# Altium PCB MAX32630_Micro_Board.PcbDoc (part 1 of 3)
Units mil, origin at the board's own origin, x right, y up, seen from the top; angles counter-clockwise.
Board outline 1192.91 x 1079.23 mil, 6 copper layers (Top Layer, Ground Plane +, Mid-Layer 2, Mid-Layer 3, Power Plane 1.8v, Bottom Layer), stack 51.6 mil thick; 105 components, 122 nets, 1109 pads, 512 vias.
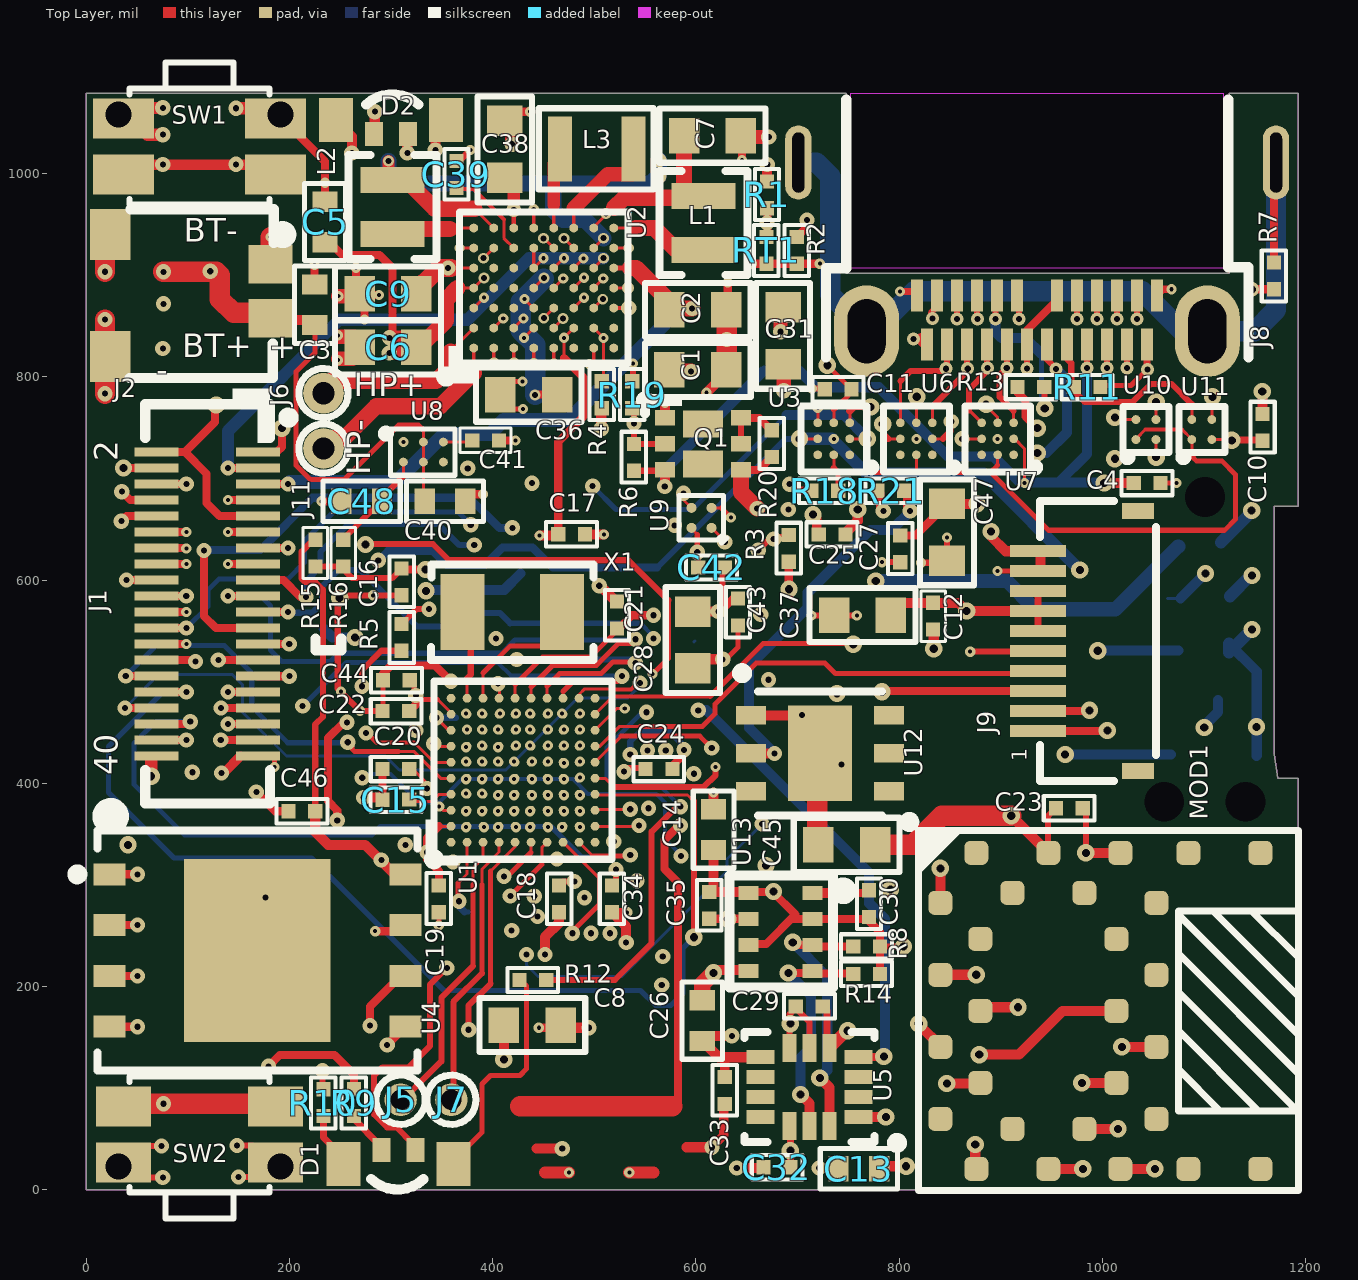
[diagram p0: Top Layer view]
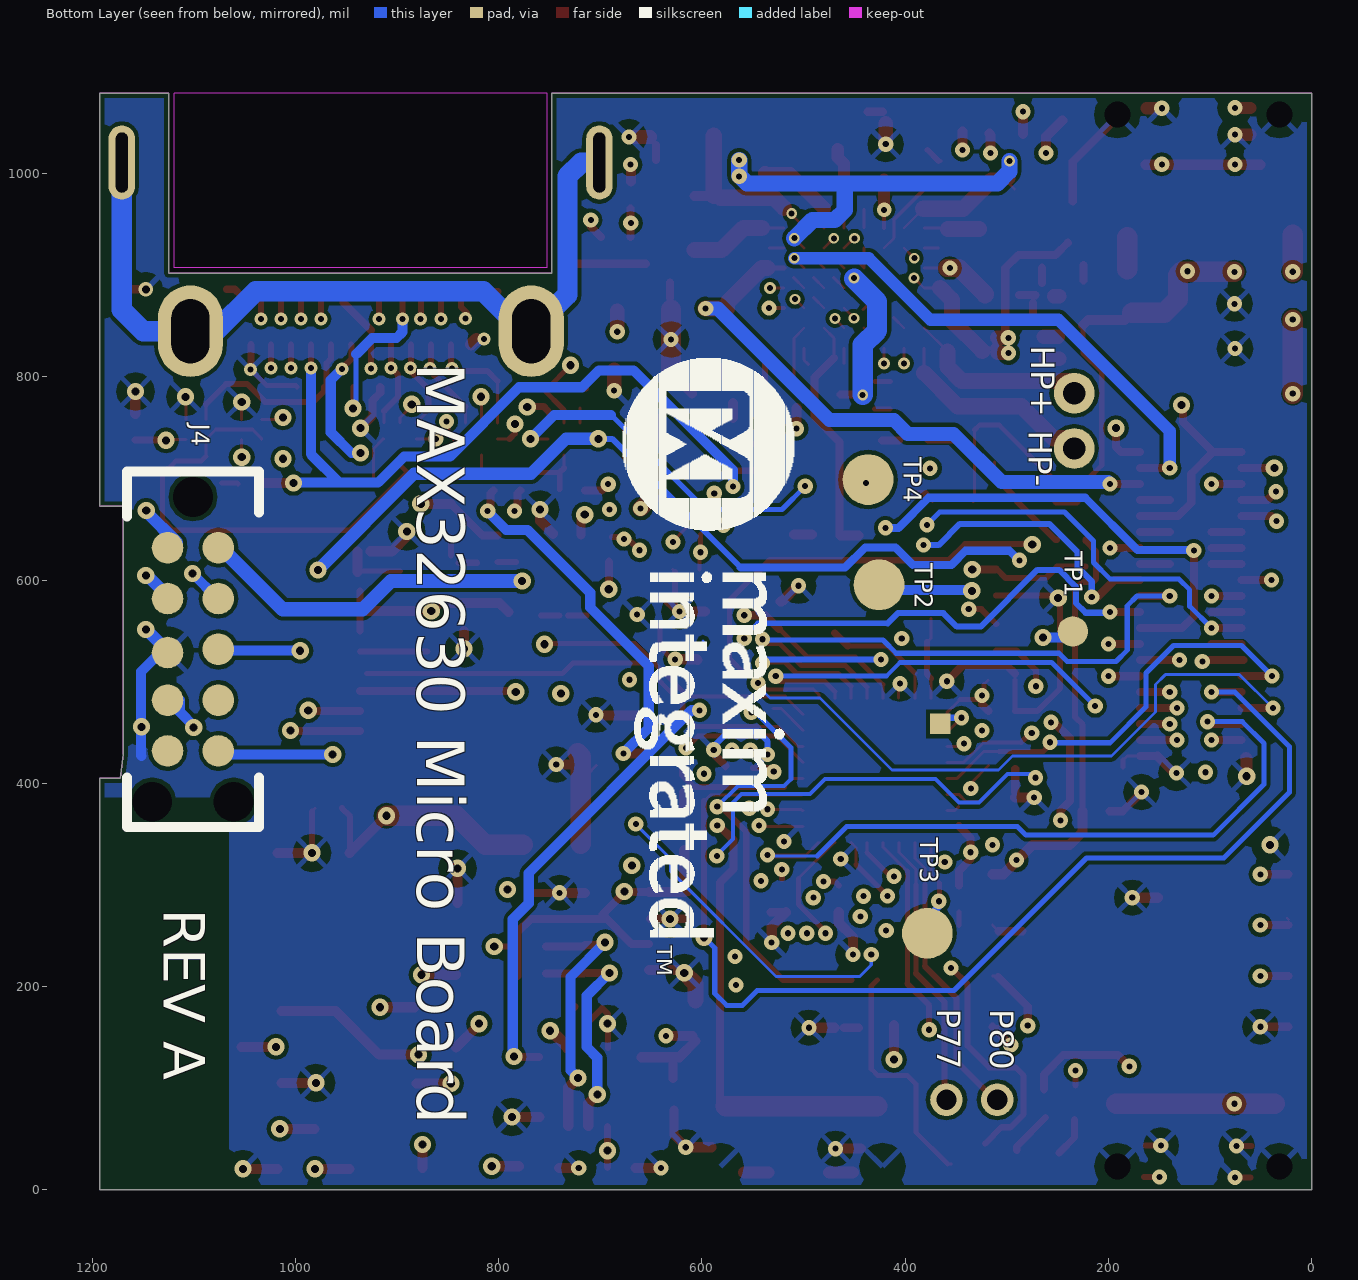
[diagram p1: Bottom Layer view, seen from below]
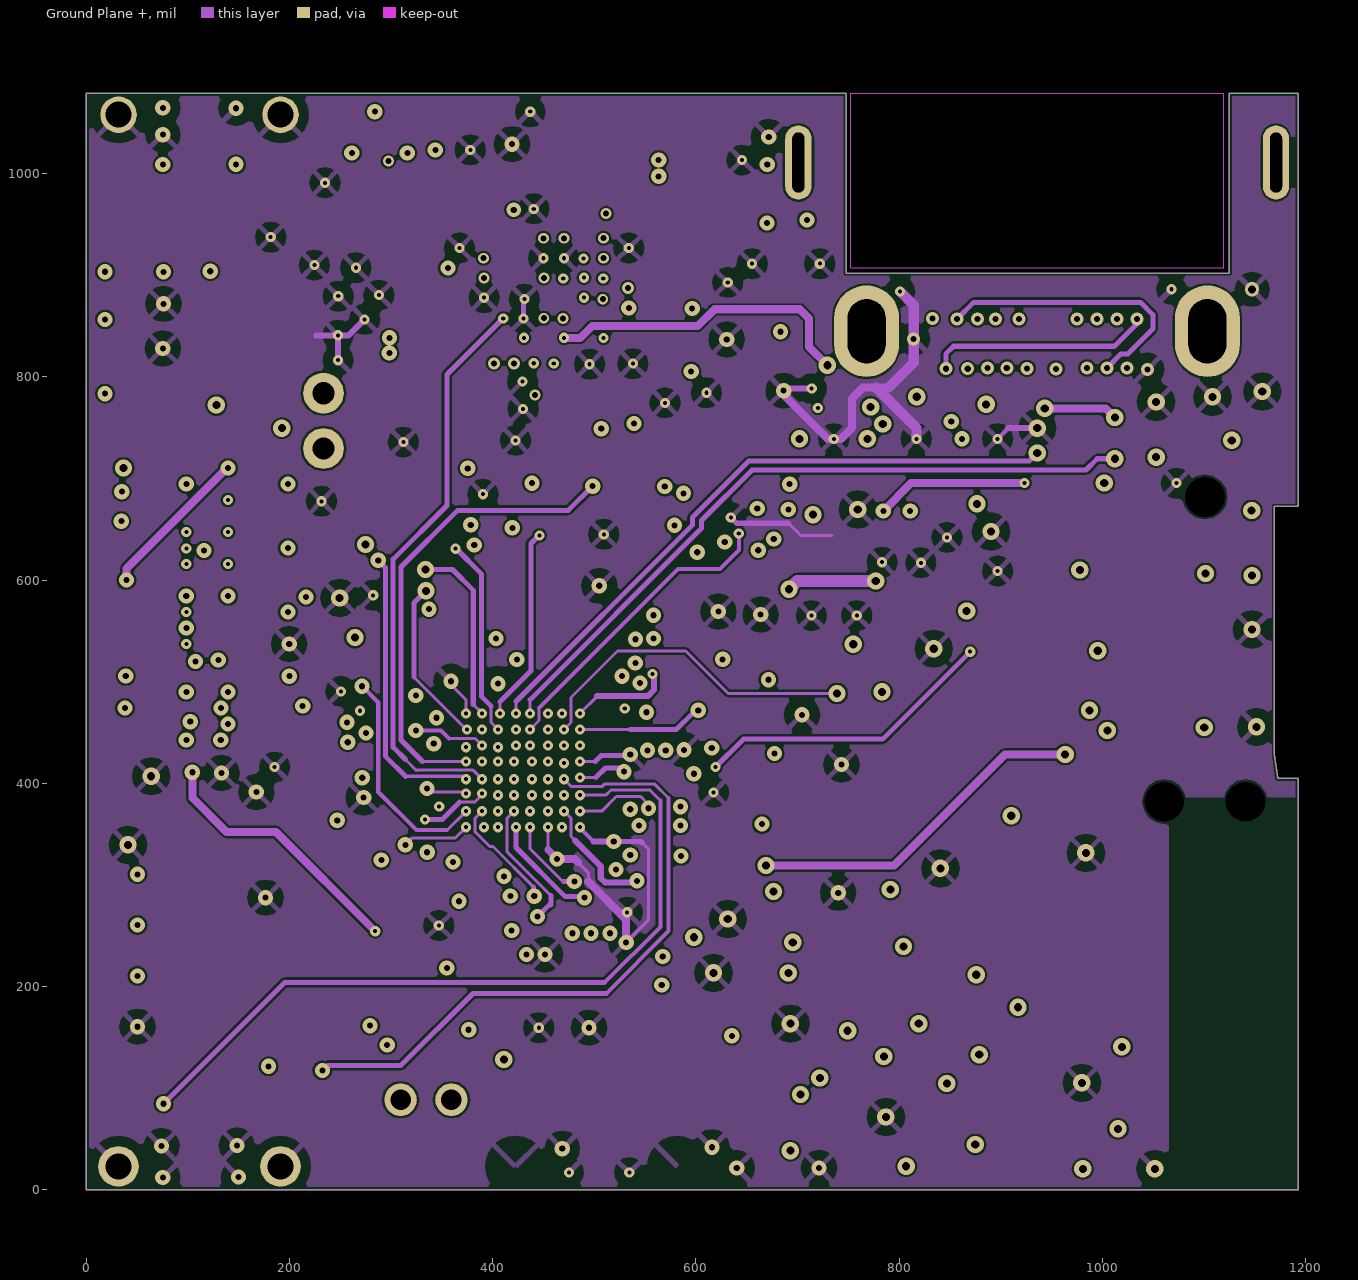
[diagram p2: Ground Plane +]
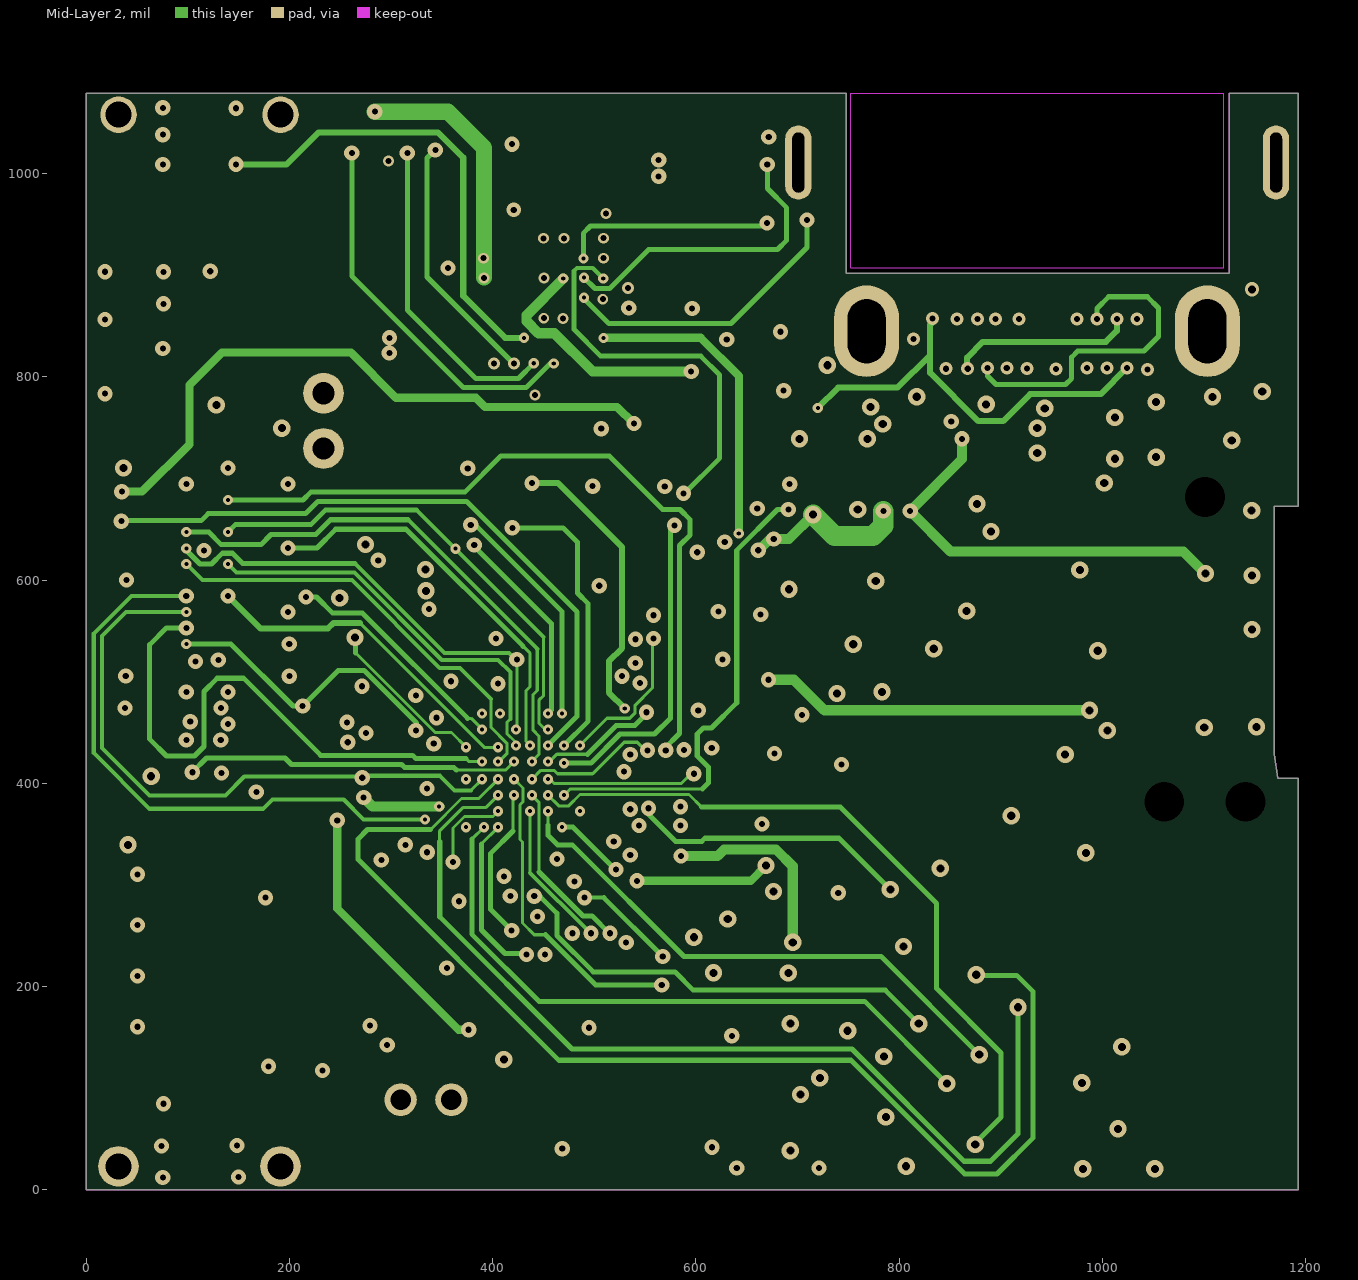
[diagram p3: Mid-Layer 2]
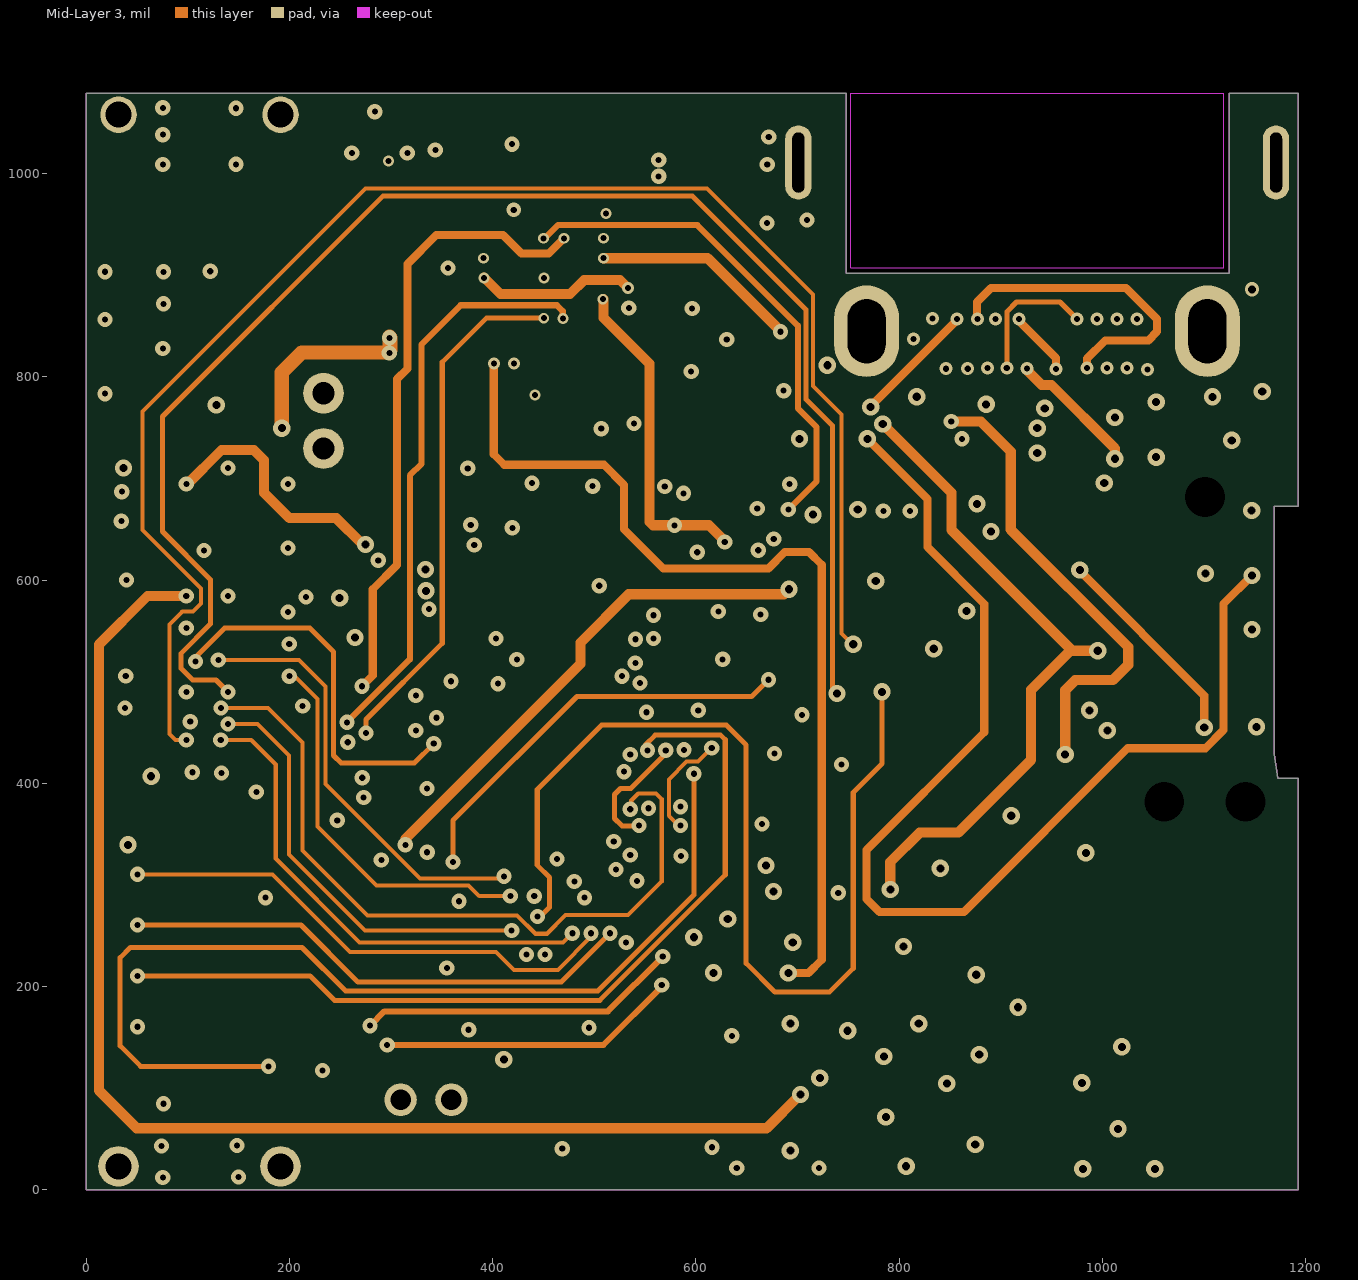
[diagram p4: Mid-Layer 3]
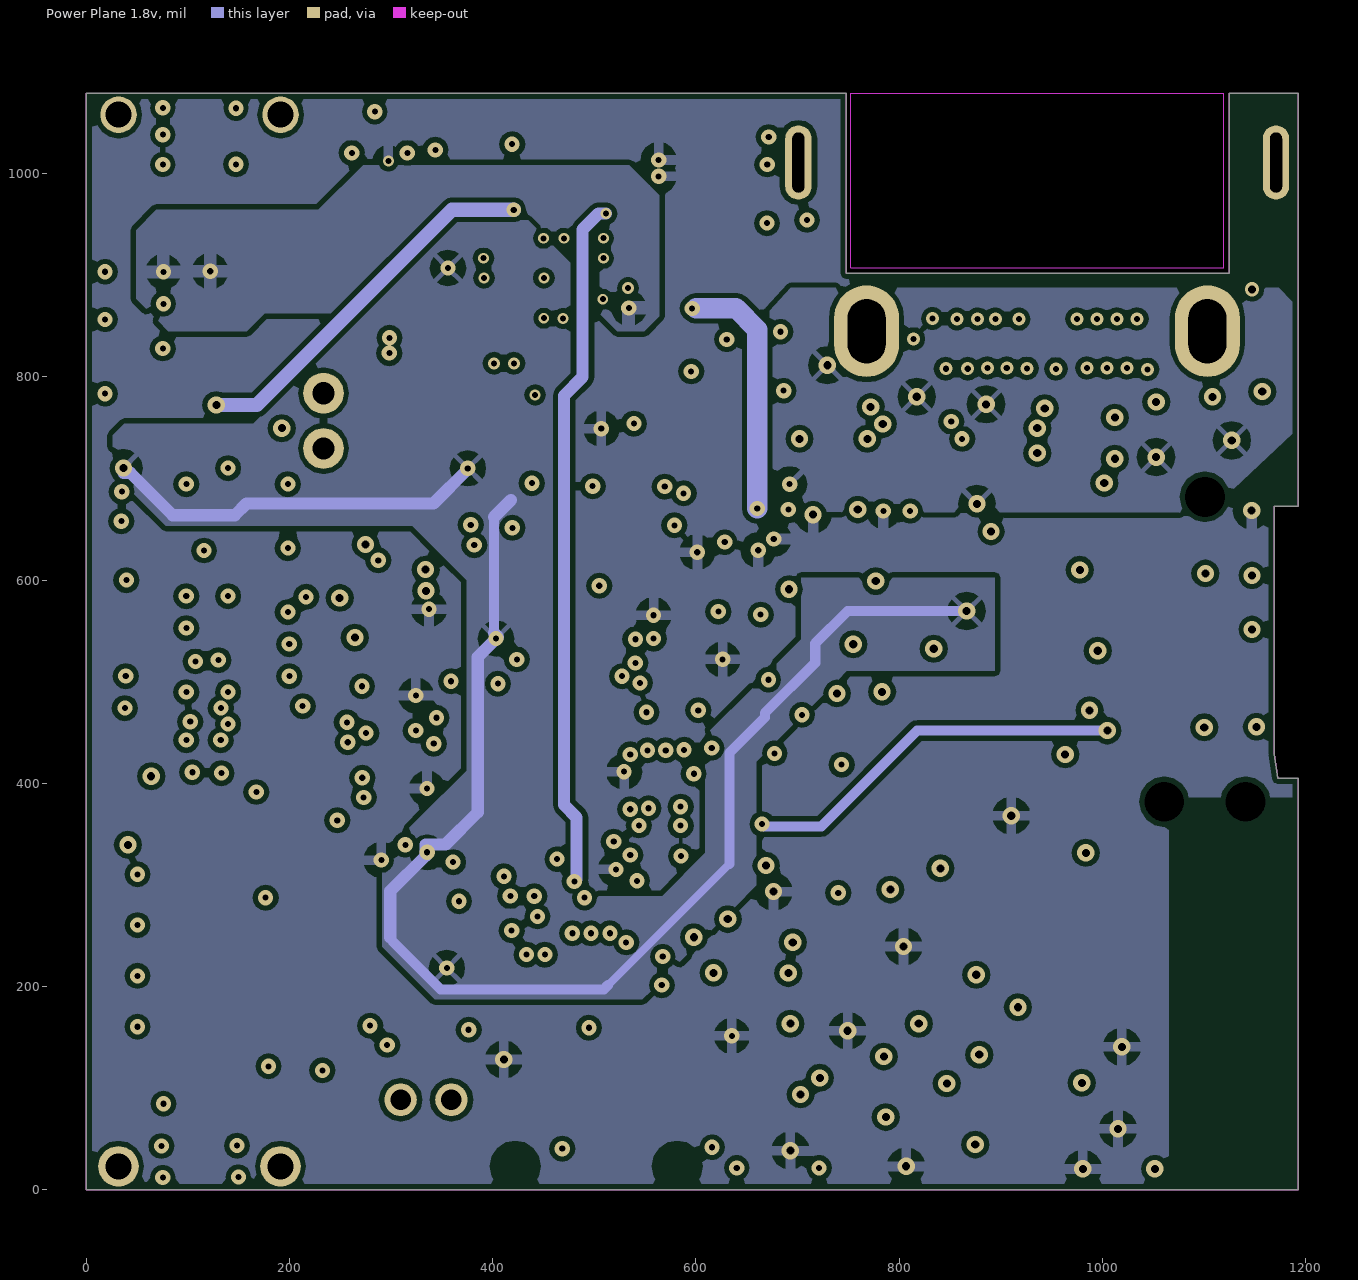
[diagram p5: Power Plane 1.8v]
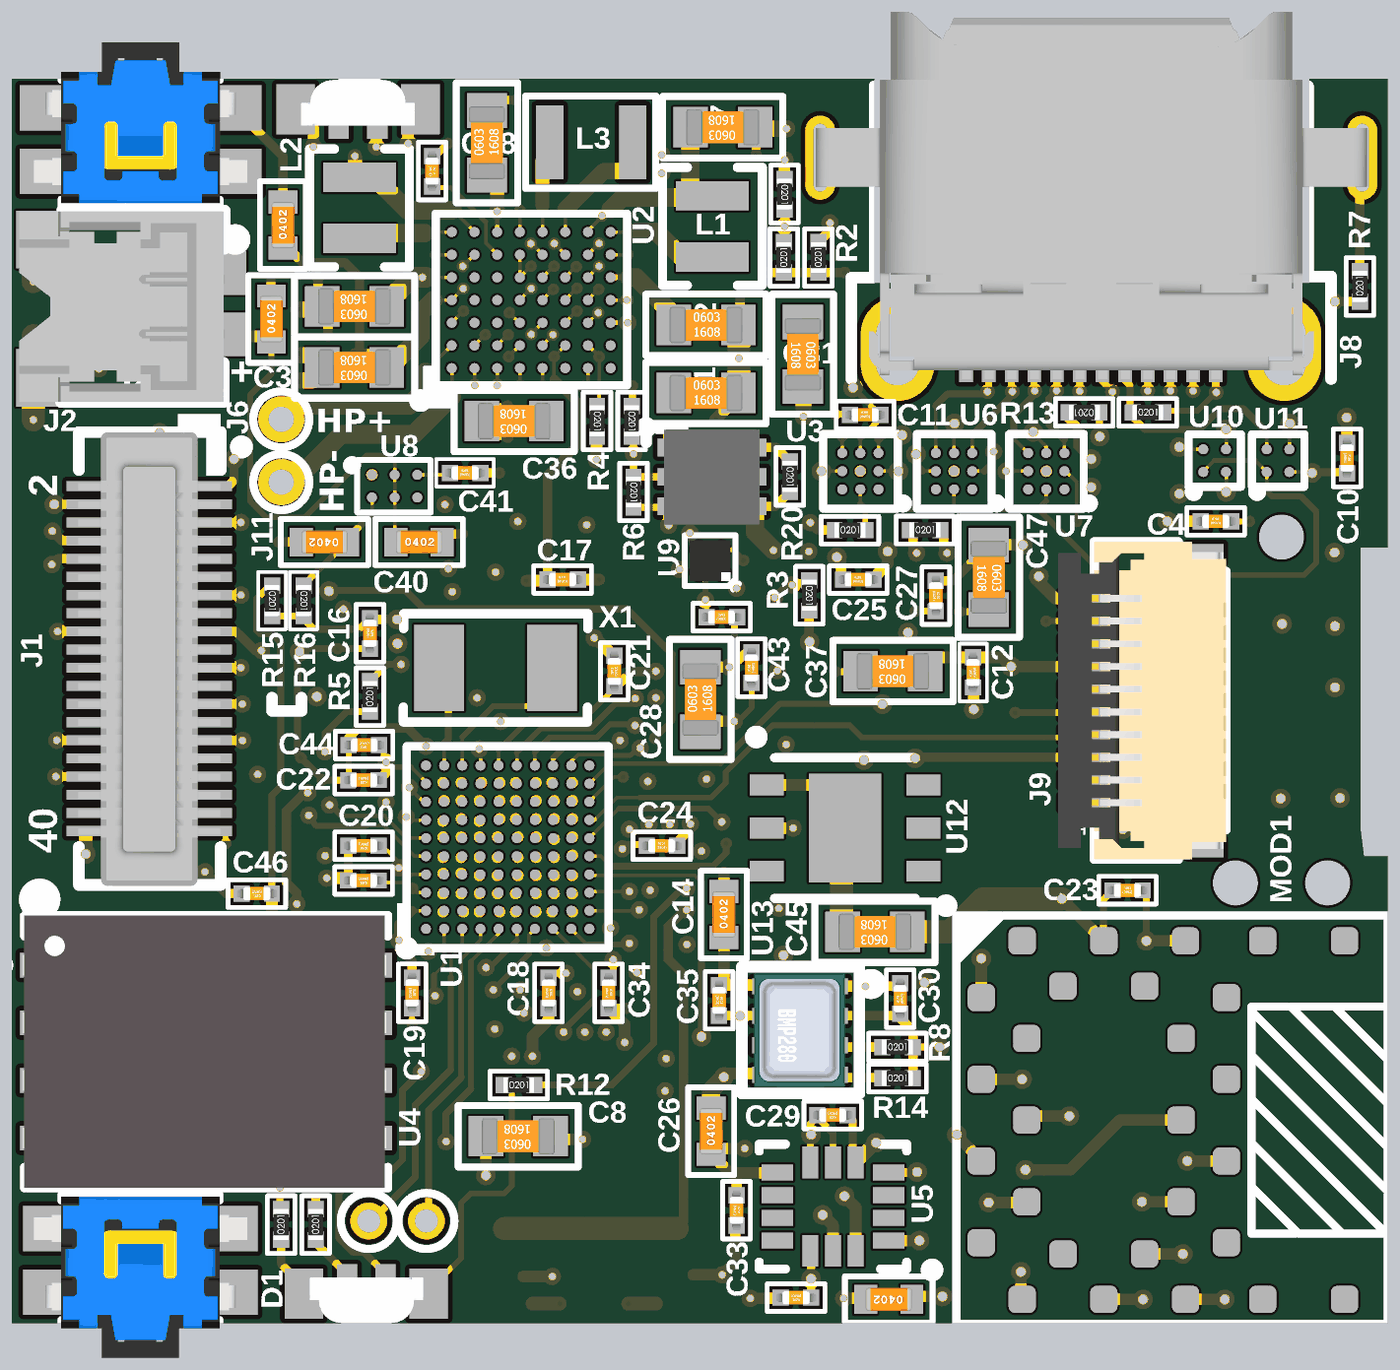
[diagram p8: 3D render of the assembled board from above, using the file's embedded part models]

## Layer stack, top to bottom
Top Solder: solder mask 0.4, Solder Resist, Dk 3.5
Top Layer: signal copper 1.4
Dielectric1: core 6, FR-4, Dk 4.8
Ground Plane +: signal copper 1.4
Dielectric2: prepreg 12.6, FR-4, Dk 4.8
Mid-Layer 2: signal copper 1.4
Dielectric3: core 6, FR-4, Dk 4.8
Mid-Layer 3: signal copper 1.4
Dielectric4: prepreg 12.6, FR-4, Dk 4.8
Power Plane 1.8v: signal copper 1.4
Dielectric5: core 6, FR-4, Dk 4.8
Bottom Layer: signal copper 1.4
Bottom Solder: solder mask 0.4, Solder Resist, Dk 3.5

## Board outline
748,902.22 748,1079.23 0,1079.23 0,0 1192.91,0 1192.91,405 1172.5,405 1169.5,428.73 1169.5,672.5 1192.91,672.5 1192.91,1079.23 1125,1079.23 1125,902.22

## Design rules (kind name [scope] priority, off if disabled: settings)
Clearance "Clearance_Bottom Layer" [OnLayer('Bottom Layer')] p1: gap=4 ignorepadtopadclearanceinfootprint=FALSE except(0: Arc-Hole Track-Hole SMDPad-Hole THPad-Hole Via-Hole Fill-Hole Poly-Hole Region-Hole Text-Hole)
Clearance "Clearance Power Plane" [OnLayer('Power Plane 1.8v')] p2: gap=5 ignorepadtopadclearanceinfootprint=FALSE except(0: Arc-Hole Track-Hole SMDPad-Hole THPad-Hole Via-Hole Fill-Hole Poly-Hole Region-Hole Text-Hole)
Clearance "Clearance Ground Plane" [(OnLayer('Ground Plane +') AND InNamedPolygon('GND'))] p3: gap=7 ignorepadtopadclearanceinfootprint=FALSE except(0: Arc-Hole Track-Hole SMDPad-Hole THPad-Hole Via-Hole Fill-Hole Poly-Hole Region-Hole Text-Hole)
Clearance [All] p4: gap=2.08 ignorepadtopadclearanceinfootprint=FALSE except(0: Arc-Hole Track-Hole SMDPad-Hole THPad-Hole Via-Hole Fill-Hole Poly-Hole Region-Hole Text-Hole)
ComponentClearance [All] p1: gap=0 collisioncheckmode=3 verticalgap=0 showdistances=FALSE
HoleSize [All] p1: absolutevalues=TRUE maxlimit=200 minlimit=4 maxpercent=80.000 minpercent=20.000
HoleToHoleClearance [All] p1: gap=9 allowstackedmicrovias=TRUE
MinimumAnnularRing [All] p1: minimumring=2
MinimumSolderMaskSliver [All] p1: minsoldermaskwidth=0
PlaneConnect [All] p1: planeconnectstyle=Relief reliefexpansion=20 reliefentries=4 reliefconductorwidth=7 reliefairgap=10
PolygonConnect PolygonConnect_3 [All vs IsNamedPolygon('BAT')] p1: connectstyle=Relief reliefconductorwidth=13 reliefentries=4 polygonreliefangle="90 Angle" airgapwidth=10
PolygonConnect PolygonConnect_2 [All vs IsNamedPolygon('PP_1V8')] p2: connectstyle=Relief reliefconductorwidth=10 reliefentries=4 polygonreliefangle="90 Angle" airgapwidth=10
PolygonConnect PolygonConnect_1 [All vs IsNamedPolygon('POWERPLANE_1V8')] p3: connectstyle=Relief reliefconductorwidth=10 reliefentries=4 polygonreliefangle="45 Angle" airgapwidth=10
PolygonConnect [All] p4: connectstyle=Relief reliefconductorwidth=5 reliefentries=4 polygonreliefangle="45 Angle" airgapwidth=10
RoutingVias [All] p1: holewidth=8 width=16 viastyle="Through Hole" minholewidth=4 minwidth=8 maxholewidth=28 maxwidth=50
SilkToSilkClearance [All] p1: silktosilkclearance=0
SilkToSolderMaskClearance [IsPad] p1: minsilkscreentomaskgap=0 clearancetoexposedcopper=TRUE
SolderMaskExpansion [All] p1: expansion=4
Width [All] p1: maxlimit=100 minlimit=3 preferedwidth=3 minimp=50.000000 maximp=50.000000 favimp=50.000000
23 further rules are at their usual default settings.

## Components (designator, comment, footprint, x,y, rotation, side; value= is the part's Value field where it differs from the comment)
C1 "22u" CAPACITOR_SMD_0603 601.89,806.89 r0 top
C2 "1u" CAPACITOR_SMD_0603 601.89,865.89 r0 top
C3 "2u2" CAPACITOR_SMD_0402 225,851 r90 top
C4 "100n" CAPACITOR_SMD_0201 1031,695.5 r0 top
C5 "2u2" CAPACITOR_SMD_0402 235,932.5 r90 top
C6 "22u" CAPACITOR_SMD_0603 297,829 r180 top
C7 "22u" CAPACITOR_SMD_0603 616.39,1037.39 r180 top
C8 "22u" CAPACITOR_SMD_0603 439,162 r180 top
C9 "22u" CAPACITOR_SMD_0603 297,882 r180 top
C10 "100n" CAPACITOR_SMD_0201 1157.78,763.5 r270 top
C11 "100N" CAPACITOR_SMD_0201 726.89,787.89 r0 top
C12 "100n" CAPACITOR_SMD_0201 833.5,551.39 r90 top
C13 "100n" CAPACITOR_SMD_0402 780.39,20.49 r180 top
C14 "100n" CAPACITOR_SMD_0402 617.39,334.39 r90 top (schematic designator C19)
C15 "100n" CAPACITOR_SMD_0201 317.89,383.89 r180 top
C16 "1u" CAPACITOR_SMD_0201 310.39,611.39 r270 top
C17 "1u" CAPACITOR_SMD_0201 464.5,645 r0 top
C18 "1u" CAPACITOR_SMD_0201 465.39,299.39 r270 top
C19 "1u" CAPACITOR_SMD_0201 347,299.5 r270 top
C20 "1u" CAPACITOR_SMD_0201 318,414 r180 top
C21 "1u" CAPACITOR_SMD_0201 522.39,552.39 r90 top
C22 "1u" CAPACITOR_SMD_0201 318,471 r180 top
C23 "100n" CAPACITOR_SMD_0201 954.39,375.39 r0 top (schematic designator C19)
C24 "100n" CAPACITOR_SMD_0201 550.5,414 r0 top (schematic designator C19)
C25 "100n" CAPACITOR_SMD_0201 720.89,644.89 r0 top (schematic designator C19)
C26 "2u2" CAPACITOR_SMD_0402 606.39,146.39 r90 top (schematic designator C1)
C27 "100n" CAPACITOR_SMD_0201 801.25,644 r270 top
C28 "4u7" CAPACITOR_SMD_0603 597,541 r90 top
C29 "100n" CAPACITOR_SMD_0201 724.78,180.39 r180 top
C30 "100n" CAPACITOR_SMD_0201 770.39,268.39 r90 top
C31 "22u" CAPACITOR_SMD_0603 685.89,840.39 r270 top
C32 "100n" CAPACITOR_SMD_0201 693,22 r180 top
C33 "100n" CAPACITOR_SMD_0201 628.39,110.84 r270 top
C34 "100n" CAPACITOR_SMD_0201 517.39,299.39 r270 top
C35 "100n" CAPACITOR_SMD_0201 613.25,293 r270 top
C36 "4u7" CAPACITOR_SMD_0603 435.5,782.5 r180 top
C37 "22u" CAPACITOR_SMD_0603 764,565.5 r180 top
C38 "22u" CAPACITOR_SMD_0603 411.89,1023.89 r90 top
C39 "100n" CAPACITOR_SMD_0201 364.39,1012.39 r270 top
C40 "2u2" CAPACITOR_SMD_0402 333,677.5 r0 top
C41 "10n" CAPACITOR_SMD_0201 379.88,737.5 r0 top
C42 "100n" CAPACITOR_SMD_0201 602.39,612.39 r0 top
C43 "100n" CAPACITOR_SMD_0201 641.39,555.39 r90 top
C44 "100n" CAPACITOR_SMD_0201 318.39,501.39 r180 top
C45 "10u" CAPACITOR_SMD_0603 748.39,339.39 r180 top
C46 "100n" CAPACITOR_SMD_0201 225.39,372.52 r180 top
C47 "22u" CAPACITOR_SMD_0603 847.15,647 r270 top (schematic designator C37)
C48 "2u2" CAPACITOR_SMD_0402 291,677.5 r180 top
D1 "APFA2507QBDSEEZGKC" LED_APFA2507QBDSEEZGKC 361.39,25.39 r180 top
D2 "APFA2507QBDSEEZGKC" LED_APFA2507QBDSEEZGKC 246,1053 r0 top
J1 "501745-0401 PLUG" 501745-0401 119,576.39 r270 top
J2 "0781710002" CONN_MOLEX_781710002 181.5,906 r0 top
J4 "TC2050-IDC-NL" TC2050-IDC-NL 1101,681.82 r270 bottom
J5 "SCL" SOLDERPAD_THD#1 309.39,88.5 r0 top
J6 "HAPTIC+" SOLDERPAD_THD#2 233.5,784 r180 top
J7 "SDA" SOLDERPAD_THD#1 359.39,88.5 r0 top
J8 "1-2295018-2" CONN_USB_1-2295018-2 1044,832.97 r180 top locked
J9 "CONN_FLEX_687110182122" 687110182122 980,540 r90 top locked
J11 "HAPTIC-" SOLDERPAD_THD#2 233.5,729.5 r180 top
L1 "2.2uH" 0806INDUCTOR 607.39,951.39 r90 top
L2 "2.2uH" 0806INDUCTOR 301.39,967.39 r90 top
L3 "4u7" INDUCTOR_0806 502.39,1024.39 r180 top
MOD1 "PAN1326B" PAN1326B-BLUETOOTH 1193,176 r270 top
Q1 "NTLJD3119CTBG" WDFN6 607,734 r0 top
R1 "10K" RESISTOR_SMD_0201 670,979.19 r270 top
R2 "39K" RESISTOR_SMD_0201 699.39,924.58 r90 top
R3 "10K" RESISTOR_SMD_0201 691.39,631.19 r270 top (schematic designator R9)
R4 "10K" RESISTOR_SMD_0201 507.39,782.39 r270 top
R5 "10K" RESISTOR_SMD_0201 310.39,543.58 r90 top
R6 "33K" RESISTOR_SMD_0201 539,720.81 r270 top
R7 "10R" RESISTOR_SMD_0201 1169,899.44 r90 top
R8 "3K3" RESISTOR_SMD_0201 768.08,239.39 r0 top
R9 "1K" RESISTOR_SMD_0201 263.39,85.58 r90 top
R10 "1K" RESISTOR_SMD_0201 233.39,85.58 r90 top
R11 "5K1" RESISTOR_SMD_0201 985.19,790 r0 top
R12 "1K" RESISTOR_SMD_0201 439.58,206.39 r0 top
R13 "5K1" RESISTOR_SMD_0201 929.81,790 r180 top
R14 "3K3" RESISTOR_SMD_0201 768.08,212.39 r0 top
R15 "0R" RESISTOR_SMD_0201 225.5,626.5 r270 top
R16 "0R" RESISTOR_SMD_0201 253,626.5 r270 top
R18 "4K7" RESISTOR_SMD_0201 726.89,687.89 r0 top
R19 "18K" RESISTOR_SMD_0201 537.39,782.39 r270 top
R20 "10K" RESISTOR_SMD_0201 674.61,734.19 r270 top
R21 "499R" RESISTOR_SMD_0201 792,688 r0 top
RT1 "10K NTC" RESISTOR_SMD_0201 669.39,924.58 r90 top
SW1 "434331013822" 434331013822#1 111.5,1026.5 r180 top
SW2 "434331013822" 434331013822#2 111.39,54.39 r0 top
TP1 "TP" TP7#1 234.93,550.39 r0 bottom
TP2 "TP" TP7#2 425.65,595.35 r180 bottom
TP3 "TP" TP7#2 378.17,252.39 r270 bottom
TP4 "TP" TP7#2 436.5,698.83 r270 bottom
U1 "MAX32630IWG+T" "WLP100 4X4MM 0.4MMP MOD1" 429.88,412.79 r90 top
U2 "MAX20303BEWN+" "WLP56 0.5MMP" 450.28,887.44 r90 top
U3 "MAX14689EWL+T" WLP9 735.75,739 r180 top
U4 "IS25WP256D-JLLE" WSON8_6x8 168.39,235.39 r0 top
U5 "BMI160" "LGA14 3x2.5MM" 712,101 r180 top (schematic designator U6)
U6 "MAX14689EWL+T" WLP9 817,739 r180 top
U7 "MAX14689EWL+T" WLP9 897,739 r180 top
U8 "MAX8532EBT2+" UCSP6 332,726 r0 top
U9 "SN74LVC1G04YZVR" DSBGA4_S-XBGA-N4_YZV 605.55,661.23 r180 top
U10 "MAX9062EBS" UCSP4 1043,748.16 r90 top
U11 "MAX9062EBS" UCSP4 1098,748.16 r90 top
U12 "DS28EL22Q+U" "TDFN6 3MM .95" 722.39,429.39 r0 top (schematic designator U5)
U13 "BMP280" BMP280 683.5,253.76 r0 top
X1 "32.768KHz" CRYSTAL-ABS07 419.39,568.39 r180 top

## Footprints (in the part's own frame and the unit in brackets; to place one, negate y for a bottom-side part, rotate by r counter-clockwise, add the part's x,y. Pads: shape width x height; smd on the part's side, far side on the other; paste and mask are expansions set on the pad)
0806INDUCTOR [mm]
  rect 0.65x1.6 smd mask+0.051: 1(-0.675,0) 2(0.675,0)
  silkscreen extent -1.3,-1.1 1.3,1.1, body extent -1,-0.8 1,0.8, height 0.95
501745-0401 [mm] "0.40mm Pitch SlimStack™ Board-to-Board Plug, Surface Mount, Dual Row, Vertical, 40 Circuits"
  rect 0.22x1.1 smd: 1(-3.8,1.27) 2(-3.8,-1.27) 3(-3.4,1.27) 4(-3.4,-1.27) 5(-3,1.27) 6(-3,-1.27) 7(-2.6,1.27) 8(-2.6,-1.27) 9(-2.2,1.27) 10(-2.2,-1.27) 11(-1.8,1.27) 12(-1.8,-1.27) 13(-1.4,1.27) 14(-1.4,-1.27) 15(-1,1.27) 16(-1,-1.27) 17(-0.6,1.27) 18(-0.6,-1.27) 19(-0.2,1.27) 20(-0.2,-1.27) 21(0.2,1.27) 22(0.2,-1.27) 23(0.6,1.27) 24(0.6,-1.27) 25(1,1.27) 26(1,-1.27) 27(1.4,1.27) 28(1.4,-1.27) 29(1.8,1.27) 30(1.8,-1.27) 31(2.2,1.27) 32(2.2,-1.27) 33(2.6,1.27) 34(2.6,-1.27) 35(3,1.27) 36(3,-1.27) 37(3.4,1.27) 38(3.4,-1.27) 39(3.8,1.27) 40(3.8,-1.27)
  silkscreen extent -4.99,-1.55 4.99,1.57, body extent -4.99,-1.56 5.01,1.57, height 1.69
434331013822#1 [mm] "WS-TASU 3.5x2.9 mm SMD side push"
  rect 1.524x1 smd: 1(-1.9,0.7) 2(1.9,0.7) 3(-1.9,-0.7) 4(1.9,-0.7)
  round 0 / inner round 0.914 / far side round 0 hole 0.65: 3(-2.025,-0.8) 4(2.025,-0.8)
  silkscreen extent -1.75,-2.1 1.75,1.45, body extent -2.35,-2.15 2.35,1.4, height 1.37
434331013822#2 [mm] "WS-TASU 3.5x2.9 mm SMD side push"
  rect 1.372x1 smd: 1(-1.9,0.7) 2(1.9,0.7) 3(-1.9,-0.7) 4(1.9,-0.7)
  round 0 / inner round 1.016 / far side round 0 hole 0.65: 3(-2.025,-0.8) 4(2.025,-0.8)
  silkscreen extent -1.75,-2.1 1.75,1.45, body extent -2.35,-2.15 2.35,1.4, height 1.37
687110182122 [mm] "0.50 mm SMT ZIF Horizontal Dual Contact, 10p"
  rect 0.3x1.397 smd: 1(-2.25,1.1) 2(-1.75,1.1) 3(-1.25,1.1) 4(-0.75,1.1) 5(-0.25,1.1) 6(0.25,1.1) 7(0.75,1.1) 8(1.25,1.1) 9(1.75,1.1) 10(2.25,1.1)
  rect 0.4x0.8 smd: ""(-3.25,-1.4) ""(3.25,-1.4)
  silkscreen extent -3.5,-1.85 3.5,1.05, body extent -3.5,-1.85 3.5,1.85, height 0.98
BMP280 [mm] "Digital Pressure Sensor"
  rect 0.5x0.35 smd: 1(0.8,0.975) 2(0.8,0.325) 3(0.8,-0.325) 4(0.8,-0.975) 5(-0.8,-0.975) 6(-0.8,-0.325) 7(-0.8,0.325) 8(-0.8,0.975)
  silkscreen extent -1.28,-1.39 1.67,1.41, body extent -1.01,-1.24 0.99,1.26, height 1
CAPACITOR_SMD_0201 [mil] "SMD 0201 Chip Capacitor"
  rect 14x14 smd: 1(0,0) 2(26.39,0)
  silkscreen extent -12,-12 38,12, body extent -4,-6 30,6, height 12
CAPACITOR_SMD_0402 [mil] "0402 SMD Ceramic Capacitor"
  rect 20x25 smd mask+2: 1(0,0) 2(40,0)
  silkscreen extent -18,-20 58,20, body extent 0,-10 40,10, height 20
CAPACITOR_SMD_0603 [mil] "SMD 0603 Chip Capacitor"
  rect 30x35 smd mask+2: 1(-28,0) 2(28,0)
  silkscreen extent -52,-27 52,27, body extent -31,-16 32,16, height 31
CONN_MOLEX_781710002 [mil] "Pico-EZmate Wire-to-Board Header, Vertical, Housing Height 1.55mm, with Side Friction Locks, 2 Circuits"
  rect 40x50 smd mask+2: 0(-158,-86) 0(-158,34)
  rect 43.31x38 smd mask+2: 1(0,5) 2(0,-48.31)
  silkscreen extent -139,-107 18,59, body extent -175,-107 3,58, height 57
CONN_USB_1-2295018-2 [mm] "TE Connectivity USB TYPE C, REC OFFSET 0.65MM DUAL SMT"
  oval 0.66x1.854 hole 0.3 slot 1.5 at 90 deg: 0(-3.226,-4.521) 0(8.714,-4.521)
  oval 1.626x2.286 hole 0.95 slot 1.6 at 90 deg: 0(-1.51,-0.305) 0(7.01,-0.305)
  rect 0.3x0.8 smd: A1(0,0.025) A2(0.5,0.025) A3(1,0.025) A4(1.5,0.025) A5(2,0.025) A6(2.5,0.025) A7(3,0.025) A8(3.5,0.025) A9(4,0.025) A10(4.5,0.025) A11(5,0.025) A12(5.5,0.025) B1(5.75,-1.2) B2(5.25,-1.2) B3(4.75,-1.2) B4(4.25,-1.2) B5(3.75,-1.2) B6(3.25,-1.2) B7(2.25,-1.2) B8(1.75,-1.2) B9(1.25,-1.2) B10(0.75,-1.2) B11(0.25,-1.2) B12(-0.25,-1.2)
  silkscreen extent -2.54,-6.1 8.03,0.36, body extent -3.33,-7.74 8.81,0.36, height 2.44
CRYSTAL-ABS07 [mm] "2 PIN SMT CRYSTAL"
  rect 1.1x1.9 smd mask+0.051: 1(-1.245,0) 2(1.245,0)
  silkscreen extent -2.03,-1.19 2.03,1.19, body extent -1.6,-0.75 1.6,0.75, height 0.9
DSBGA4_S-XBGA-N4_YZV [mm] "Die Sized Ball Grid Array"
  round 0.25 smd: A1(-0.25,0.25) A2(0.25,0.25) B1(-0.25,-0.25) B2(0.25,-0.25)
  silkscreen extent -0.63,-0.56 0.56,0.63, body extent -0.45,-0.45 0.45,0.45, height 0.6
INDUCTOR_0806 [mm] "0806 (2016) SMD Inductor"
  rect 0.6x1.63 smd: 1(-0.914,0) 2(0.914,0)
  silkscreen extent -1.42,-1.02 1.45,1.02, body extent -1.03,-0.81 1.07,0.81, height 1.05
LED_APFA2507QBDSEEZGKC [mm] "2.5 x 0.7 mm Right Angle SMD Chip LED Lamp"
  rect 0.85x1.1 smd: 1(0,0) 4(2.75,0)
  rect 0.45x0.6 smd: 2(0.95,-0.35) 3(1.8,-0.35)
  silkscreen extent 0.75,0.38 2.06,0.64, body extent 0.12,-0.36 2.62,0.64, height 0.7
"LGA14 3x2.5MM" [mm]
  rect 0.7x0.35 smd mask+0.051: 1(-1.225,0.75) 2(-1.225,0.25) 3(-1.225,-0.25) 4(-1.225,-0.75) 8(1.225,-0.75) 9(1.225,-0.25) 10(1.225,0.25) 11(1.225,0.75)
  rect 0.35x0.7 smd mask+0.051: 5(-0.5,-0.975) 6(0,-0.975) 7(0.5,-0.975) 12(0.5,0.975) 13(0,0.975) 14(-0.5,0.975)
  silkscreen extent -2.31,-1.37 1.63,1.52, body extent -1.5,-1.25 1.5,1.25, height 0.84
PAN1326B-BLUETOOTH [mm]
  rrect50% 0.6x0.6 smd mask+0.05: 1(-2.7,-8.95) 2(-1.8,-7.95) 3(-0.9,-8.95) 4(0,-7.95) 5(0.9,-8.95) 6(1.8,-7.95) 7(2.7,-8.95) 8(3.95,-8.05) 9(2.95,-7.15) 10(3.95,-6.25) 11(2.95,-5.35) 12(3.95,-4.45) 13(2.7,-3.55) 14(1.8,-4.55) 15(0.9,-3.55) 16(0,-4.55) 17(-0.9,-3.55) 18(-1.8,-4.55) 19(-2.7,-3.55) 20(-3.95,-4.45) 21(-2.95,-5.35) 22(-3.95,-6.25) 23(-2.95,-7.15) 24(-3.95,-8.05) A(-3.95,-2.75) B(3.95,-2.75) C(-3.95,-0.95) D(3.95,-0.95)
  silkscreen extent -4.85,-9.85 4.49,0.01, body extent -4.51,-9.5 4.49,0, height 1.7
RESISTOR_SMD_0201 [mil] "SMD 0201 Chip Resistor"
  rect 14x14 smd: 1(-13.19,0) 2(13.19,0)
  silkscreen extent -25,-12 25,12, body extent -14,-6 13,6, height 13
SOLDERPAD_THD#1 [mil] "Soldering Hole"
  round 32 hole 20: 1(0,0)
  silkscreen extent -24,-24 24,24
SOLDERPAD_THD#2 [mil] "Soldering Hole"
  round 40 hole 22: 1(0,0)
  silkscreen extent -24,-24 24,24
TC2050-IDC-NL [mm] "Tag-Connect 10-Pin with No Legs (PN# TC2050-IDC-NL)"
  round 0.9 hole 0.995 unplated: 0(0,0) 0(7.62,-1.016) 0(7.62,1.016)
  round 0.79 smd paste-0.39: 1(1.27,-0.635) 2(2.54,-0.635) 3(3.89,-0.635) 4(5.08,-0.635) 5(6.35,-0.635) 6(6.35,0.635) 7(5.08,0.635) 8(3.81,0.635) 9(2.54,0.635) 10(1.27,0.635)
  silkscreen extent -0.64,-1.65 8.25,1.65
"TDFN6 3MM .95" [mm]
  rect 0.75x0.46 smd mask+0.051: 1(-1.725,0.95) 2(-1.725,0) 3(-1.725,-0.95) 4(1.725,-0.95) 5(1.725,0) 6(1.725,0.95)
  rect 1.6x2.39 smd mask+0.051: EP(0,0)
  silkscreen extent -2.08,-1.55 1.55,2.13, body extent -1.55,-1.55 1.55,1.55, height 0.8
TP7#1 [mil]
  round 30 smd paste-65 mask+2: 1(0,1)
TP7#2 [mil]
  round 50 smd paste-65 mask+2: 1(0,0)
UCSP4 [mil] "UCSP4"
  round 8.66 smd mask+1.97: A1(-9.84,9.84) A2(9.84,9.84) B1(-9.84,-9.84) B2(9.84,-9.84)
  round 1 on Mech4 mask+2: ""(-6.79,5.02) ""(-6.79,-10.73) ""(-6.79,6.79) ""(-6.79,-8.96) ""(-5.02,5.02) ""(-5.02,6.79) ""(-5.02,-10.73) ""(-5.02,-8.96) ""(8.96,-10.73) ""(8.96,5.02) ""(8.96,-8.96) ""(8.96,6.79) ""(10.73,-10.73) ""(10.73,-8.96) ""(10.73,5.02) ""(10.73,6.79)
  silkscreen extent -30,-23 23,23, body extent -17,-17 17,17, height 25
UCSP6 [mm] "UCSP6"
  round 0.22 smd mask+0.05: A1(-0.504,0.25) A2(-0.004,0.25) A3(0.496,0.25) B1(-0.504,-0.25) B2(-0.004,-0.25) B3(0.496,-0.25)
  silkscreen extent -1.02,-0.58 0.79,0.58, body extent -0.69,-0.43 0.69,0.43, height 0.63
WDFN6 [mm] "WDFN6"
  rect 0.5x0.39 smd: 1(-0.95,0.65) 2(-0.95,0) 3(-0.95,-0.65) 4(0.95,-0.65) 5(0.95,0) 6(0.95,0.65)
  rect 1x0.67 smd: 7(0,-0.5) 8(0,0.5)
  silkscreen extent -1.55,0.76 -1.04,1.19, body extent -1.05,-1.05 1.05,1.05, height 0.77
WLP9 [mil] "WLP9"
  round 8.66 smd mask+1.97: A1(-15.75,15.75) A2(0,15.75) A3(15.75,15.75) B1(-15.75,0) B2(0,0) B3(15.75,0) C1(-15.75,-15.75) C2(0,-15.75) C3(15.75,-15.75)
  round 1 on Mech4 mask+2: ""(-16.63,14.86) ""(-16.63,-0.88) ""(-16.63,-16.63) ""(-16.63,16.63) ""(-16.63,0.88) ""(-16.63,-14.86) ""(-14.86,14.86) ""(-14.86,16.63) ""(-14.86,-0.88) ""(-14.86,0.88) ""(-14.86,-16.63) ""(-14.86,-14.86) ""(-0.88,14.86) ""(-0.88,-0.88) ""(-0.88,-16.63) ""(-0.88,16.63) ""(-0.88,0.88) ""(-0.88,-14.86) ""(0.88,16.63) ""(0.88,14.86) ""(0.88,0.88) ""(0.88,-0.88) ""(0.88,-14.86) ""(0.88,-16.63) ""(14.86,14.86) ""(14.86,-0.88) ""(14.86,-16.63) ""(14.86,16.63) ""(14.86,0.88) ""(14.86,-14.86) ""(16.63,14.86) ""(16.63,16.63) ""(16.63,-0.88) ""(16.63,0.88) ""(16.63,-16.63) ""(16.63,-14.86)
  silkscreen extent -40,-32 32,32, body extent -23,-23 23,23, height 25
"WLP56 0.5MMP" [mm] "WLP 56  0.5mm Pitch"
  round 0.22 smd mask+0.05: A1(-1.5,1.75) A2(-1,1.75) A3(-0.5,1.75) A4(0,1.75) A5(0.5,1.75) A6(1,1.75) A7(1.5,1.75) B1(-1.5,1.25) B2(-1,1.25) B3(-0.5,1.25) B4(0,1.25) B5(0.5,1.25) B6(1,1.25) B7(1.5,1.25) C1(-1.5,0.75) C2(-1,0.75) C3(-0.5,0.75) C4(0,0.75) C5(0.5,0.75) C6(1,0.75) C7(1.5,0.75) D1(-1.5,0.25) D2(-1,0.25) D3(-0.5,0.25) D4(0,0.25) D5(0.5,0.25) D6(1,0.25) D7(1.5,0.25) E1(-1.5,-0.25) E2(-1,-0.25) E3(-0.5,-0.25) E4(0,-0.25) E5(0.5,-0.25) E6(1,-0.25) E7(1.5,-0.25) F1(-1.5,-0.75) F2(-1,-0.75) F3(-0.5,-0.75) F4(0,-0.75) F5(0.5,-0.75) F6(1,-0.75) F7(1.5,-0.75) G1(-1.5,-1.25) G2(-1,-1.25) G3(-0.5,-1.25) G4(0,-1.25) G5(0.5,-1.25) G6(1,-1.25) G7(1.5,-1.25) H1(-1.5,-1.75) H2(-1,-1.75) H3(-0.5,-1.75) H4(0,-1.75) H5(0.5,-1.75) H6(1,-1.75) H7(1.5,-1.75)
  round 0.025 on Mech4 mask+0.051: ""(-1.522,1.727) ""(-1.522,-1.073) ""(-1.522,-1.073) ""(-1.522,1.772) ""(-1.522,-1.028) ""(-1.522,-1.028) ""(-1.477,1.727) ""(-1.477,1.772) ""(-1.477,-1.073) ""(-1.477,-1.073) ""(-1.477,-1.028) ""(-1.477,-1.028)
  silkscreen extent -2.34,-2.11 1.9,2.56, body extent -1.67,-1.93 1.68,1.92, height 0.63
"WLP100 4X4MM 0.4MMP MOD1" [mil] "for ME04 MAX32630"
  round 8.66 smd mask+1.97: A1(-70.87,70.87) A2(-55.12,70.87) A3(-39.37,70.87) A4(-23.62,70.87) A5(-7.87,70.87) A6(7.87,70.87) A7(23.62,70.87) A8(39.37,70.87) A9(55.12,70.87) A10(70.87,70.87) B1(-70.87,55.12) B2(-55.12,55.12) B3(-39.37,55.12) B4(-23.62,55.12) B5(-7.87,55.12) B6(7.87,55.12) B7(23.62,55.12) B8(39.37,55.12) B9(55.12,55.12) B10(70.87,55.12) C1(-70.87,39.37) C2(-55.12,39.37) C3(-39.37,39.37) C4(-23.62,39.37) C5(-7.87,39.37) C6(7.87,39.37) C7(23.62,39.37) C8(39.37,39.37) C9(55.12,39.37) C10(70.87,39.37) D1(-70.87,23.62) D2(-55.12,23.62) D3(-39.37,23.62) D4(-23.62,23.62) D5(-7.87,23.62) D6(7.87,23.62) D7(23.62,23.62) D8(39.37,23.62) D9(55.12,23.62) D10(70.87,23.62) E1(-70.87,7.87) E2(-55.12,7.87) E3(-39.37,7.87) E4(-23.62,7.87) E5(-7.87,7.87) E6(7.87,7.87) E7(23.62,7.87) E8(39.37,7.87) E9(55.12,7.87) E10(70.87,7.87) F1(-70.87,-7.87) F2(-55.12,-7.87) F3(-39.37,-7.87) F4(-23.62,-7.87) F5(-7.87,-7.87) F6(7.87,-7.87) F7(23.62,-7.87) F8(39.37,-7.87) F9(55.12,-7.87) F10(70.87,-7.87) G1(-70.87,-23.62) G2(-55.12,-23.62) G3(-39.37,-23.62) G4(-23.62,-23.62) G5(-7.87,-23.62) G6(7.87,-23.62) G7(23.62,-23.62) G8(39.37,-23.62) G9(55.12,-23.62) G10(70.87,-23.62) H1(-70.87,-39.37) H2(-55.12,-39.37) H3(-39.37,-39.37) H4(-23.62,-39.37) H5(-7.87,-39.37) H6(7.87,-39.37) H7(23.62,-39.37) H8(39.37,-39.37) H9(55.12,-39.37) H10(70.87,-39.37) J1(-70.87,-55.12) J2(-55.12,-55.12) J3(-39.37,-55.12) J4(-23.62,-55.12) J5(-7.87,-55.12) J6(7.87,-55.12) J7(23.62,-55.12) J8(39.37,-55.12) J9(55.12,-55.12) J10(70.87,-55.12) K1(-70.87,-70.87) K2(-55.12,-70.87) K3(-39.37,-70.87) K4(-23.62,-70.87) K5(-7.87,-70.87) K6(7.87,-70.87) K7(23.62,-70.87) K8(39.37,-70.87) K9(55.12,-70.87) K10(70.87,-70.87)
  round 1 on Mech4 mask+2: ""(-71.75,-71.75) ""(-71.75,-56) ""(-71.75,-40.25) ""(-71.75,-24.51) ""(-71.75,-8.76) ""(-71.75,6.99) ""(-71.75,22.74) ""(-71.75,38.49) ""(-71.75,54.23) ""(-71.75,69.98) ""(-71.75,-69.98) ""(-71.75,-54.23) ""(-71.75,-38.49) ""(-71.75,-22.74) ""(-71.75,-6.99) ""(-71.75,8.76) ""(-71.75,24.51) ""(-71.75,40.25) ""(-71.75,56) ""(-71.75,71.75) ""(-69.98,-71.75) ""(-69.98,-69.98) ""(-69.98,-56) ""(-69.98,-54.23) ""(-69.98,-40.25) ""(-69.98,-38.49) ""(-69.98,-24.51) ""(-69.98,-22.74) ""(-69.98,-8.76) ""(-69.98,-6.99) ""(-69.98,6.99) ""(-69.98,8.76) ""(-69.98,22.74) ""(-69.98,24.51) ""(-69.98,38.49) ""(-69.98,40.25) ""(-69.98,54.23) ""(-69.98,56) ""(-69.98,69.98) ""(-69.98,71.75) ""(-56,69.98) ""(-56,-56) ""(-56,-40.25) ""(-56,-24.51) ""(-56,-8.76) ""(-56,6.99) ""(-56,22.74) ""(-56,38.49) ""(-56,54.23) ""(-56,-71.75) ""(-56,71.75) ""(-56,-54.23) ""(-56,-38.49) ""(-56,-22.74) ""(-56,-6.99) ""(-56,8.76) ""(-56,24.51) ""(-56,40.25) ""(-56,56) ""(-56,-69.98) ""(-54.23,69.98) ""(-54.23,71.75) ""(-54.23,-56) ""(-54.23,-54.23) ""(-54.23,-40.25) ""(-54.23,-38.49) ""(-54.23,-24.51) ""(-54.23,-22.74) ""(-54.23,-8.76) ""(-54.23,-6.99) ""(-54.23,6.99) ""(-54.23,8.76) ""(-54.23,22.74) ""(-54.23,24.51) ""(-54.23,38.49) ""(-54.23,40.25) ""(-54.23,54.23) ""(-54.23,56) ""(-54.23,-71.75) ""(-54.23,-69.98) ""(-40.25,69.98) ""(-40.25,-56) ""(-40.25,-40.25) ""(-40.25,-24.51) ""(-40.25,-8.76) ""(-40.25,6.99) ""(-40.25,22.74) ""(-40.25,38.49) ""(-40.25,54.23) ""(-40.25,-71.75) ""(-40.25,71.75) ""(-40.25,-54.23) ""(-40.25,-38.49) ""(-40.25,-22.74) ""(-40.25,-6.99) ""(-40.25,8.76) ""(-40.25,24.51) ""(-40.25,40.25) ""(-40.25,56) ""(-40.25,-69.98) ""(-38.49,69.98) ""(-38.49,71.75) ""(-38.49,-56) ""(-38.49,-54.23) ""(-38.49,-40.25) ""(-38.49,-38.49) ""(-38.49,-24.51) ""(-38.49,-22.74) ""(-38.49,-8.76) ""(-38.49,-6.99) ""(-38.49,6.99) ""(-38.49,8.76) ""(-38.49,22.74) ""(-38.49,24.51) ""(-38.49,38.49) ""(-38.49,40.25) ""(-38.49,54.23) ""(-38.49,56) ""(-38.49,-71.75) ""(-38.49,-69.98) ""(-24.51,38.49) ""(-24.51,54.23) ""(-24.51,69.98) ""(-24.51,-24.51) ""(-24.51,-8.76) ""(-24.51,6.99) ""(-24.51,22.74) ""(-24.51,-71.75) ""(-24.51,-56) ""(-24.51,-40.25) ""(-24.51,40.25) ""(-24.51,56) ""(-24.51,71.75) ""(-24.51,-22.74) ""(-24.51,-6.99) ""(-24.51,8.76) ""(-24.51,24.51) ""(-24.51,-69.98) ""(-24.51,-54.23) ""(-24.51,-38.49) ""(-22.74,38.49) ""(-22.74,40.25) ""(-22.74,54.23) ""(-22.74,56) ""(-22.74,69.98) ""(-22.74,71.75) ""(-22.74,-24.51) ""(-22.74,-22.74) ""(-22.74,-8.76) ""(-22.74,-6.99) ""(-22.74,6.99) ""(-22.74,8.76) ""(-22.74,22.74) ""(-22.74,24.51) ""(-22.74,-71.75) ""(-22.74,-69.98) ""(-22.74,-56) ""(-22.74,-54.23) ""(-22.74,-40.25) ""(-22.74,-38.49) ""(-8.76,54.23) ""(-8.76,69.98) ""(-8.76,22.74) ""(-8.76,38.49) ""(-8.76,-8.76) ""(-8.76,6.99) ""(-8.76,-40.25) ""(-8.76,-24.51) ""(-8.76,-71.75) ""(-8.76,-56) ""(-8.76,56) ""(-8.76,71.75) ""(-8.76,24.51) ""(-8.76,40.25) ""(-8.76,-6.99) ""(-8.76,8.76) ""(-8.76,-38.49) ""(-8.76,-22.74) ""(-8.76,-69.98) ""(-8.76,-54.23) ""(-6.99,69.98) ""(-6.99,71.75) ""(-6.99,54.23) ""(-6.99,56) ""(-6.99,38.49) ""(-6.99,40.25) ""(-6.99,22.74) ""(-6.99,24.51) ""(-6.99,8.76) ""(-6.99,-6.99) ""(-6.99,6.99) ""(-6.99,-8.76) ""(-6.99,-24.51) ""(-6.99,-22.74) ""(-6.99,-40.25) ""(-6.99,-38.49) ""(-6.99,-56) ""(-6.99,-54.23) ""(-6.99,-71.75) ""(-6.99,-69.98) ""(6.99,69.98) ""(6.99,54.23) ""(6.99,38.49) ""(6.99,22.74) ""(6.99,6.99) ""(6.99,-8.76) ""(6.99,-24.51) ""(6.99,-40.25) ""(6.99,-56) ""(6.99,-71.75) ""(6.99,71.75) ""(6.99,56) ""(6.99,40.25) ""(6.99,24.51) ""(6.99,8.76) ""(6.99,-6.99) ""(6.99,-22.74) ""(6.99,-38.49) ""(6.99,-54.23) ""(6.99,-69.98) ""(8.76,54.23) ""(8.76,56) ""(8.76,69.98) ""(8.76,71.75) ""(8.76,22.74) ""(8.76,24.51) ""(8.76,38.49) ""(8.76,40.25) ""(8.76,-8.76) ""(8.76,-6.99) ""(8.76,6.99) ""(8.76,8.76) ""(8.76,-40.25) ""(8.76,-38.49) ""(8.76,-24.51) ""(8.76,-22.74) ""(8.76,-71.75) ""(8.76,-69.98) ""(8.76,-56) ""(8.76,-54.23) ""(22.74,38.49) ""(22.74,54.23) ""(22.74,69.98) ""(22.74,-24.51) ""(22.74,-8.76) ""(22.74,6.99) ""(22.74,22.74) ""(22.74,-71.75) ""(22.74,-56) ""(22.74,-40.25) ""(22.74,40.25) ""(22.74,56) ""(22.74,71.75) ""(22.74,-22.74) ""(22.74,-6.99) ""(22.74,8.76) ""(22.74,24.51) ""(22.74,-69.98) ""(22.74,-54.23) ""(22.74,-38.49) ""(24.51,38.49) ""(24.51,40.25) ""(24.51,54.23) ""(24.51,56) ""(24.51,69.98) ""(24.51,71.75) ""(24.51,-24.51) ""(24.51,-22.74) ""(24.51,-8.76) ""(24.51,-6.99) ""(24.51,6.99) ""(24.51,8.76) ""(24.51,22.74) ""(24.51,24.51) ""(24.51,-71.75) ""(24.51,-69.98) ""(24.51,-56) ""(24.51,-54.23) ""(24.51,-40.25) ""(24.51,-38.49) ""(38.49,69.98) ""(38.49,-56) ""(38.49,-40.25) ""(38.49,-24.51) ""(38.49,-8.76) ""(38.49,6.99) ""(38.49,22.74) ""(38.49,38.49) ""(38.49,54.23) ""(38.49,-71.75) ""(38.49,71.75) ""(38.49,-54.23) ""(38.49,-38.49) ""(38.49,-22.74) ""(38.49,-6.99) ""(38.49,8.76) ""(38.49,24.51) ""(38.49,40.25) ""(38.49,56) ""(38.49,-69.98) ""(40.25,69.98) ""(40.25,71.75) ""(40.25,-56) ""(40.25,-54.23) ""(40.25,-40.25) ""(40.25,-38.49) ""(40.25,-24.51) ""(40.25,-22.74) ""(40.25,-8.76) ""(40.25,-6.99) ""(40.25,6.99) ""(40.25,8.76) ""(40.25,22.74) ""(40.25,24.51) ""(40.25,38.49) ""(40.25,40.25) ""(40.25,54.23) ""(40.25,56) ""(40.25,-71.75) ""(40.25,-69.98) ""(54.23,69.98) ""(54.23,-56) ""(54.23,-40.25) ""(54.23,-24.51) ""(54.23,-8.76) ""(54.23,6.99) ""(54.23,22.74) ""(54.23,38.49) ""(54.23,54.23) ""(54.23,-71.75) ""(54.23,71.75) ""(54.23,-54.23) ""(54.23,-38.49) ""(54.23,-22.74) ""(54.23,-6.99) ""(54.23,8.76) ""(54.23,24.51) ""(54.23,40.25) ""(54.23,56) ""(54.23,-69.98) ""(56,69.98) ""(56,71.75) ""(56,-56) ""(56,-54.23) ""(56,-40.25) ""(56,-38.49) ""(56,-24.51) ""(56,-22.74) ""(56,-8.76) ""(56,-6.99) ""(56,6.99) ""(56,8.76) ""(56,22.74) ""(56,24.51) ""(56,38.49) ""(56,40.25) ""(56,54.23) ""(56,56) ""(56,-71.75) ""(56,-69.98) ""(69.98,-71.75) ""(69.98,-56) ""(69.98,-40.25) ""(69.98,-24.51) ""(69.98,-8.76) ""(69.98,6.99) ""(69.98,22.74) ""(69.98,38.49) ""(69.98,54.23) ""(69.98,69.98) ""(69.98,-69.98) ""(69.98,-54.23) ""(69.98,-38.49) ""(69.98,-22.74) ""(69.98,-6.99) ""(69.98,8.76) ""(69.98,24.51) ""(69.98,40.25) ""(69.98,56) ""(69.98,71.75) ""(71.75,-71.75) ""(71.75,-69.98) ""(71.75,-56) ""(71.75,-54.23) ""(71.75,-40.25) ""(71.75,-38.49) ""(71.75,-24.51) ""(71.75,-22.74) ""(71.75,-8.76) ""(71.75,-6.99) ""(71.75,6.99) ""(71.75,8.76) ""(71.75,22.74) ""(71.75,24.51) ""(71.75,38.49) ""(71.75,40.25) ""(71.75,54.23) ""(71.75,56) ""(71.75,69.98) ""(71.75,71.75)
  silkscreen extent -93,-88 88,93, body extent -78,-78 78,78, height 25
WSON8_6x8 [mm] "SON,1.27mm,pitch; 8 pin,8.00mm W X 6.00mm L X 1.00mm H body (w/pullback leads,thermal tab 3.4 X 4mm), IPC Medium Density"
  rect 0.8x0.55 smd: 1(-3.7,1.905) 2(-3.7,0.635) 3(-3.7,-0.635) 4(-3.7,-1.905) 5(3.7,-1.905) 6(3.7,-0.635) 7(3.7,0.635) 8(3.7,1.905)
  rect 3.659x4.583 smd: EP(0,0)
  silkscreen extent -4.62,-3 4,3, body extent -4.04,-2.99 3.96,3.01, height 0.78

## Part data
C1 C6 C7 C8 C9 C31 C37 C38 C47: library part CAP_0603_22u, "CAP CER 22UF 6.3V X5R 0603"
C2: library part CAP_0603_1u, "CAP CER 1UF 16V X5R 0603"
C3 C5 C26 C40 C48: library part CAP_0402_2u2, "CAP CER 2.2UF 10V X5R 0402"
C4 C10 C11 C12 C15 C23 C24 C25 C27 C29 C30 C32 C33 C34 C35 C39 C42 C43 C44 C46: library part CAP_0201_100n, "CAP CER 0.1UF 10V X5R 0201"
C13 C14: library part CAP_0402_100n, "CAP CER 0.1UF 16V X7R 0402"
C16 C17 C18 C19 C20 C21 C22: library part CAP_0201_1u, "CAP CER 1UF 10V X6S 0201"
C28 C36: library part CAP_0603_4u7, "CAP CER 4.7UF 10V X5R 0603"
C41: library part CAP_0201_10n, "CAP CER 10000PF 10V X7R 0201"
C45: library part CAP_0603_10u, "CAP CER 10UF 16V X5R 0603"
D1 D2: library part LED_APFA2507QBDSEEZGKC, "2.5 x 0.7 mm Right Angle SMD Chip LED Lamp"
J1: library part CONN_MOLEX_5017450401, "CONN PLUG 40POS 0.4MM SMD GOLD"
J2: library part CONN_MOLEX_0781710002, "1.20MM WTB HEADER VERT 2POS"
J4: library part "JUMPBLOCK 5", "CONN HEADER 10POS DUAL .05\" SMD"
J5 J6 J7 J11: library part SolderPad_TH, "PCB Pad"
J8: library part CONN_USB_1-2295018-2, "TE Connectivity USB TYPE C, REC OFFSET 0.65MM DU"
J9: "0.50 mm SMT ZIF Horizontal Dual Contact WR-FPC, 10 pins"
L1 L2: library part INDUCTOR1, "INDUCTOR 2.2UH 1.5A 160 MOHM"
L3: library part INDUCTOR1, "INDUCTOR 4.7UH 1.5A 160 mOHM"
MOD1: "BLUETOOTH PAN1326B CC2564B HCI A"
Q1: "20 V/-20 V, 4.6 A/-4.1 A, Complementary Power MOSFET"
R1 R3 R4 R5 R20: library part RES_0201_10K, "RES SMD 10K OHM 1% 1/20W 0201"
R2: library part RES_0201_39K, "RES SMD 39K OHM 1% 1/20W 0201"
R6: library part RES_0201_33K, "RES SMD 33K OHM 1% 1/20W 0201"
R7: library part RES_0201_10R, "RES SMD 10 OHM 1% 1/20W 0201"
R8 R14: library part RES_0201_3K3, "RES SMD 3K3 OHM 5% 1/20W 0201"
R9 R10 R12: library part RES_0201_1K, "RES SMD 1K OHM 1% 1/20W 0201"
R11 R13: library part RES_0201_5K1, "RES SMD 5K1 OHM 1% 1/20W 0201"
R15 R16: library part RES_0201_0R, "RES SMD 0 OHM JUMPER 1/20W 0201"
R18: library part RES_0201_4K7, "RES SMD 4.7K OHM 1% 1/20W 0201"
R19: library part RES_0201_18K, "RES SMD 18K OHM 1% 1/20W 0201"
R21: library part RES_0201_499R, "RES SMD 499R 5% 1/20W 0201"
RT1: library part THERMISTOR_0201_10K, "NTC THERMISTOR 10K OHM 1% 0201"
SW1 SW2: library part SW-PB-434331013822, "SWITCH TACTILE SPST-NO 0.02A 15V"
TP1 TP2 TP3 TP4: "Test Point"
U1: "Ultra-Low Power Cortex-M4F Microcontroller for Rechargeable Devices"
U2: "Wearable PMIC"
U3 U6 U7: "Ultra-Small, Low-RON, Beyond-the-Rails DPDT Analog Switches"
U4: "IC FLASH 256M SPI 104MHZ 8WSON"
U5: library part BMi160, "Inertial Measurement Unit, Low Power 14pin"
U8: "IC REG LINEAR 200MA 6-UCSP"
U9: "SN74LVC1G04 Single Inverter Gate"
U10 U11: library part MAX9062EBS+T, "Ultra-Small, nanoPower Single Comparators in 4-Bump UCSP"
U12: "1-WIRE SHA-256 SECURE AUTHENTICATOR WITH 2KBIT EEPROM"
U13: "Digital Pressure Sensor"
X1: library part CRYSTAL_ABS07-32.768KHZ-6-T, "CRYSTAL 32.768KHZ 6.0PF SMD"

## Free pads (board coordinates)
  round 8 on Mid1: 1(373.88,356.77) 1(389.63,404.02) 1(405.38,435.51) 1(421.13,404.02) 1(421.13,421.54) 1(438.65,421.54) 1(454.4,372.52) 1(454.4,404.02) 1(454.4,421.54) 1(454.4,468.79)
  rect 20x20 smd far side: 2(365.31,458.5)

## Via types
v1: diameter 15, hole 6, Top Layer to Bottom Layer, tented both sides, 180 vias
v2: diameter 10, hole 4, Top Layer to Ground Plane +, tented both sides, 134 vias
v3: diameter 17, hole 8, Top Layer to Bottom Layer, tented both sides, 82 vias
v4: diameter 10, hole 4, Ground Plane + to Mid-Layer 2, tented both sides, 57 vias
v5: diameter 12.8, hole 6, Top Layer to Bottom Layer, tented both sides, 20 vias
v6: diameter 10, hole 4, Top Layer to Ground Plane +, tented top, 16 vias
v7: diameter 10.63, hole 5.91, Top Layer to Bottom Layer, tented both sides, 13 vias
v8: diameter 10, hole 4, Ground Plane + to Mid-Layer 2, 5 vias
v9: diameter 11.81, hole 5.91, Top Layer to Bottom Layer, tented both sides, 3 vias
v10: diameter 14.17, hole 6, Top Layer to Bottom Layer, tented both sides, 1 vias
v11: diameter 14, hole 8, Top Layer to Bottom Layer, tented both sides, 1 vias

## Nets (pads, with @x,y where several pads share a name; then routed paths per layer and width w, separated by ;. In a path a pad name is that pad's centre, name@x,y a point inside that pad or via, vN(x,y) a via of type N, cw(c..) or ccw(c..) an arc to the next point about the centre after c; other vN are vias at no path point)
1V2: C7.2 C18.1 L1.2 U1.F2 U2.G7 | length 953
  Top Layer w3: U2.G7@499.5,946.5 499.5,947.5 518.89,966.89
  Top Layer w6: C18.1@465.39,299.39 469.39,303.39 v1(480.39,303.39)
  Top Layer w10: L1.2@588.39,977.96 L1.2@607.39,977.96
  Top Layer w16: 519.39,966.39 529.39,976.39 L1.2@581.81,976.39 ; L1.2@588.39,977.96 C7.2@588.39,1037.39
  Ground Plane + w3: v2(436.87,356.77) 436.87,335.29 469.16,303
  Ground Plane + w5: 469.54,303.39 v1(480.39,303.39)
  Power Plane 1.8v w12: v1(480.39,303.39) 482.62,305.62 482.62,366.41 470.24,378.8 470.24,781.47 488.54,799.77 488.54,945.08 504.13,960.68 v7(511.68,960.68)
1V8: C8.2 C13.1 C14.1 C20.1 C21.1 C22.1 C23.1 C24.1 C25.1 C26.1 C28.1 C29.1 C30.1 C32.1 C33.1 C34.1 C35.1 C42.1 C43.1 C44.1 C45.1 C46.1 J4.1 L2.2 MOD1.10 MOD1.11 MOD1.15 MOD1.22 R3.1 R4.2 R5.2 R8.2 R14.2 R15.1 R21.1 U1.A9 U1.B4 U1.E10 U1.H2 U1.J5 U2.B7 U2.G6 U4.8 U5.5 U5.8 U5.12 U7.B1 U9.A2 U13.2 U13.6 U13.8 | length 3112.5
  Top Layer w3: L2.2@292.43,985 L2.2@301.39,993.96 ; C20.1@318,417.4 335.55,399.85 335.38,399.68 v1@335.38,396.39 ; C22.1@318,471 C22.1@319.1,471 ; C44.1@318.39,501.39 C44.1@322.39,497.39 ; v1@322.39,488.39 v1(324.39,486.39) ; 345.89,482.39 359.02,469.26 U1.A9@359.02,467.91 ; 383.39,968.39 383.39,964.18 U2.B7@401.07,946.5 ; U1.E10@422.01,483.65 422.01,497.01 ; U2.G6@499.5,926.81 v7(509.13,936.44) v7@509.67,936.98 ; R4.2@506.64,769 R4.2@509.13,769 ; U9.A2@595.7,651.39 595.7,650.46 601.39,644.78 ; v1@600.39,627.39 v1@601.39,628.39 ; v1(601.39,627.39) v1@602.39,626.39 ; C26.1@606.39,144.61 C26.1@606.39,146.39 ; C14.1@617.39,327.76 C14.1@617.39,334.39 ; v1@672.38,640.38 v1(676.68,640.38) ; U5.5@731.68,139.39 U5.5@731.68,139.68 ; U7.B1@912.75,739 913.78,739 923.39,729.39 v6(923.39,695.39) ; MOD1.22@946.39,332.08 MOD1.22@946.95,331.51
  Top Layer w4: C42.1@602.39,610.39 v1@602.39,626.39
  Top Layer w5: v1@322.39,488.39 C44.1@322.39,497.39 ; v1@324.39,482.39 345.89,482.39 ; 422.01,497.01 449,524 496,524 C21.1@524,552 ; v1@601.39,628.39 601.39,644.78 ; v1(626.39,521.99) 629.6,521.99 641.39,533.78 C43.1@641.39,555.39
  Top Layer w6: R15.1@222.5,639.69 222.5,638.5 212,628 212,601.5 215.5,598 225.5,598 233,590.5 233,465.5 225.39,457.89 C46.1@225.39,372.52 ; R5.2@310.39,556.78 325,571.39 v1(337.39,571.39) ; C34.1@521.39,306 v1@521.39,314.39 ; v1@530,415 C24.1@549.5,415 ; v1(661.39,629.39) v1@672.38,640.38 ; v1@677.68,642.38 R3.1@688.38,642.38 ; R8.2@781.39,239.39 v3(804.39,239.39) ; MOD1.22@946.39,332.08 946.39,367.39 C23.1@954.39,375.39
  Top Layer w7: C32.1@693,22 v3(693,38.39) U5.12@693,61.93 ; C29.1@724.78,180.39 729,176.17 729,142.07 U5.5@731.68,139.39
  Top Layer w8: C22.1@318,471 324.39,477.39 324.39,482.39 v1(324.39,486.39) ; C21.1@524,552 537.39,565.39 v1(558.39,565.39) ; C35.1@613.25,293 U13.8@652.01,293 ; U13.6@652.01,241.96 669.22,241.96 698.02,270.76 675.64,293.14 U13.8@652.01,293.14 ; 693.81,266.55 U13.2@715,266.55 768.29,266.55 781.39,253.45 781.39,239.39 R14.2@781.39,210.39 ; R21.1@778.81,688 781.5,685.3 781.5,671.45 v1@785,667.95
  Top Layer w9: C33.1@628.39,109.28 628.39,130.39 645.39,130.39 ; v3(715.39,664.39) 719,660.78 C25.1@719,644.39
  Top Layer w10: C46.1@225.39,372.52 225.39,352.11 238.11,339.39 274.39,339.39 303.39,310.39 U4.8@314.06,310.39 ; v3(411,128.05) C8.2@411,162 ; R4.2@506.64,769 506.89,769.25 v1(506.89,749) ; C28.1@604.39,521.39 604.99,521.99 v1(626.39,521.99) ; C26.1@606.39,146.39 622.39,130.39 U5.8@659.39,130.39 ; C26.1@609.39,151.39 v1(635.39,151.39) ; C14.1@617.39,334.39 617.39,293.14 U13.8@652.01,293.14 ; C13.1@780.39,23 v3(806.95,23) ; v3(910.46,368) MOD1.22@946.39,332.08 ; MOD1.22@946.39,331.51 MOD1.22@946.95,331.51 ; MOD1.10@946.95,20.49 v3(980.91,20.49) ; MOD1.11@981.52,59.86 v3(1015.48,59.86) ; v3(1019.3,140.57) MOD1.15@1053.25,140.57
  Top Layer w12: L2.2@297.39,995.39 v7(297.39,1012.39) ; U5.5@731.68,139.68 748.39,156.39 v3(749.39,156.39)
  Top Layer w16: L2.2@309.39,993.39 315,993.39 343,965.39 382.18,965.39
  Top Layer w20: C45.1@776.39,339.39 813.39,339.39 842,368 v3(910.46,368)
  Ground Plane + w3: v1@335.38,396.39 335.38,395.17 339.16,391.39 372.54,391.39 v2(373.88,390.05) ; v6@485.9,405.8 501.8,405.8
  Ground Plane + w5: v6@485.9,405.8 v6@486.39,406.29 ; 501.8,405.8 511,415 v1@530,415
  Ground Plane + w8: v1(784.53,668) 811.92,695.39 v6(923.39,695.39)
  Mid-Layer 2 w5: v2(468.37,356.77) 479,356.77 v1@518.55,317.23
  Mid-Layer 2 w10: v1@661.7,629.08 673,640.39 691.39,640.39 v3(715.39,664.39)
  Mid-Layer 2 w20: v3(715.39,664.39) 736.39,643.39 774.39,643.39 784.53,653.53 v1(784.53,668)
  Bottom Layer w12: J4.1@1116.72,636.89 1147.02,667.18 v3(1147.02,668.39)
  Bottom Layer w16: v7(297.39,1012.39) 297.39,1002.22 309.22,990.39 455.18,990.39 ; v7(509.13,936.44) 491.18,954.39 469.33,954.39 459.56,964.17 459.56,986.02 455.18,990.39 ; v1(563.39,1013.39) 563.39,998.21 555.56,990.39 455.18,990.39
  other v1: 521.39,315.25 290.39,324.39 335.39,394.89 529.39,411.39 563.39,997.39
  other v3: 676.39,293.39
  other v4: 468.37,356.77
  other v6: 485.98,405.8
1V8_S: C31.1 J1.3 J1.18 U2.G5 | length 931.3
  Top Layer w3: U2.G5@499.5,907.13 v7@509.67,917.3 ; C31.1@683.39,865.39 C31.1@686.39,868.39
  Top Layer w8: v1(39.54,600.02) J1.18@69,600.02 ; v1(139.54,710.25) J1.3@169,710.25
  Top Layer w14: v1@683.39,844.97 C31.1@683.39,865.39
  Ground Plane + w8: v1(39.54,600.02) 39.54,611.37 137.53,709.36 v1@137.53,712.26
  Mid-Layer 3 w10: v7(509.13,916.76) 611.6,916.76 v1@683.39,844.97
  Bottom Layer w12: v1(139.54,710.25) 139.54,746.68 249.03,856.17 375.21,856.17 435.8,916.76 v7(509.13,916.76)
  other v1: 683.39,844.39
